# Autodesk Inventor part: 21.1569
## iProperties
Created: 2012-02
Part Number: 21.1569
Document SubType Name: Modeling
Designer: Administrator
Density: 7.85 g/cm^3
Material: Steel
Mass: 5.06207 g
Surface Area: 8.61064 cm^2
Volume: 0.644849 cm^3
Description: M6 SQUARE NUT 30
Vendor: S
Author: Administrator
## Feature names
1. Extrusion1
2. Extrusion2
3. Fillet1
4. Hole1
5. Extrusion3
6. Extrusion4
7. Fillet2
